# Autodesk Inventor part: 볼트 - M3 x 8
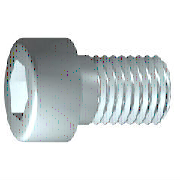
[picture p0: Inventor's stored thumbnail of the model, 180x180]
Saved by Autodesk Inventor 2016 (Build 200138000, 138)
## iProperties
IsCustomPart: 0
Created: 2012-02
Part Number: 볼트 - M3 x 8
Material: 스테인리스강
Description: 6각 소켓 머리 캡 나사
Document SubType Name: Modeling
Standard: ISO 4762
Designer: mduedu
Standard Revision: Fourth edition 2004-03-01
Standards Organization: ISO
Language: ko-KR
Size Designation: M3 x 8
Categories: <MemberInstance><Categories><Category DisplayName="조임쇠" InternalName="e4da775c-781d-43d5-af7c-5136215cf5a6" Mnemonic="FSTN"><Category DisplayName="볼트" InternalN
Density: 8.08 g/cm^3
Mass: 0.955869 g
Surface Area: 1.83001 cm^2
Volume: 0.118301 cm^3
Appearance: 반광택
Author: mduedu
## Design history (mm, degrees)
sketch "스케치1"
  geometry: L1 (-0.867, 0)-(8, 0); L2 (8, 0)-(8, 1.5); L3 (8, 1.5)-(1.25, 1.5); L4 (1.25, 1.5)-(0.943, 1.5); L5 (0.943, 1.5)-(0, 1.5); L6 (0, 1.5)-(0, 2.75); L7 (0, 2.75)-(-3, 2.75); L8 (-3, 2.75)-(-3, 1.443); L9 (-3, 1.443)-(-1.7, 1.443); L10 (-1.7, 1.443)-(-0.867, 0); L11 (-5.2, 0)-(10.2, 0) reference; L12 (0, -0.55)-(0, 3.3) reference; L13 (1.25, 1.5)-(0, 1.5)
  constraints: 22 end point, 6 parallel, 2 collinear, 2 perpendicular, 1 horizontal, 1 point on line
  dimensions: "d1" = 6.75 distance from line of L3.end L2 (= GEL); "d2" = 0.30683 distance of L4.end L3.end (computed from GAL); "d3" = 3 distance between parallel lines of L8 L6 (= KOH); "d4" = 1.3 distance of L8.end L9.end (= INTI); "d5" = 60 deg angle of L10 L1; "d6" = 3 diameter of L3 L1 (= GD); "d7" = 3 diameter of L5 L1 (= BDM); "d8" = 2.88675 diameter of L9 L1 (= 1.1547 x SW); "d9" = 5.5 diameter of L7 L1 (= KOD); "d26" = 8 distance between parallel lines of L12 L2 (= NLG)
revolve "본체" sketch "스케치1" stored, may be unused: angle "d10" = 90 deg
sketch "스케치2"
  geometry: L1 (0, -3.85)-(0, 3.85) reference; L2 (-3.85, 0)-(3.85, 0) reference; L3 (1.443, 0)-(0.722, -1.25); L4 (0.722, -1.25)-(-0.722, -1.25); L5 (-0.722, -1.25)-(-1.443, 0); L6 (-1.443, 0)-(-0.722, 1.25); L7 (-0.722, 1.25)-(0.722, 1.25); L8 (0.722, 1.25)-(1.443, 0); 2 further points
  constraints: 12 end point, 1 coincident, 1 horizontal alignment, 1 point on line, 12 other
extrude "슬롯" join sketch "스케치2" stored distance "d11" = 10; taper "d12" = 0 deg
workplane "Work Plane1"
fillet "Fillet2" dims "d30" = 0.1 (= R)
body "Solid1"
fillet "모깎기1" dims "d17" = 0.3 (= RR)
feature "스레드" dims "d13" = 6.75 (= GEL), "d14" = 0
chamfer "모따기1" distance "d15" = 0.30673 (= -0.5 x SPD + 0.5 x GD); stored, may be unused: second distance "d16" = 0.30673 (= GUL), angle "d27" = 45 deg
other parameters: "GD" = 3 [user parameter; used in 2 equation terms], "NLG" = 8 [user parameter; used in 1 equation term], "GEL" = 6.75 [user parameter; used in 2 equation terms], "KOD" = 5.5 [user parameter; used in 1 equation term], "KOH" = 3 [user parameter; used in 1 equation term], "INTI" = 1.3 [user parameter; used in 1 equation term], "GAL" = 0.30673 (= 0.61345 x PTC) [user parameter; used in 1 equation term], "GUL" = 0.30673 (= 0.61345 x PTC) [user parameter; used in 1 equation term], "BDM" = 3 (= NND) [user parameter; used in 1 equation term], "SW" = 2.5 [user parameter; used in 2 equation terms], "RR" = 0.3 [user parameter; used in 1 equation term], "SPD" = 2.38655 (= NND - 1.2269 x PTC) [user parameter; used in 1 equation term], "d19" = 0, "d28" = 0, "d29" = 0, "R" = 0.1 [user parameter; used in 1 equation term], "TOA" = 30 deg [user parameter], "GD1" = 2.38655 (= THREADDIA - 1.2269 x PTC) [user parameter], "THREADDIA" = 3 [user parameter; used in 1 equation term], "FAWI" = 45 deg [user parameter], "PTC" = 0.5 [user parameter; used in 5 equation terms], "NND" = 3 [user parameter; used in 2 equation terms], "E0" = 2.8875 (= 1.155 x SW) [user parameter]
